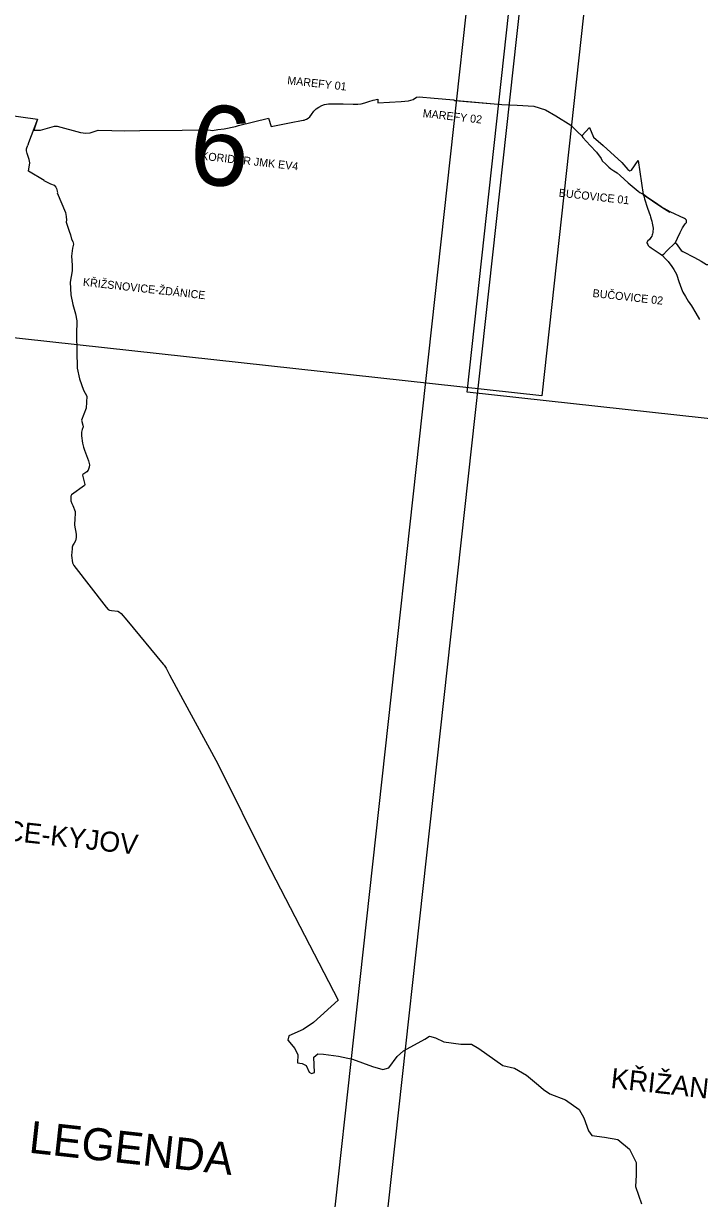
# Model space of a CAD drawing. Extents: x -678204 to -526855, y -1228851 to -1110393.
# Drawn here: x -574848 to -569781, y -1176918 to -1168109 of the extents above; entities that cross this region are included whole.
import ezdxf

# ---------------------------------------------------------------- set-up
doc = ezdxf.new("R2010")
doc.units = 0
for name, color, linetype in [('00_n_cyklo popisy detaily', 7, 'Continuous'), ('00_n_cyklo popisy ostatni', 7, 'Continuous'), ('00_n_cyklo provereni rekreacni hlavni', 7, 'Continuous'), ('00_n_cyklo provereni vedlejsi', 7, 'Continuous'), ('00_n_cyklo prujezdne rekreacni hlavni', 7, 'Continuous'), ('00_n_cyklo prujezdne rekreacni vedlejsi', 7, 'Continuous'), ('00_n_cyklo trasovani rekreacni hlavni', 7, 'Continuous'), ('00_n_cyklo trasovani rekreacni vedlejsi', 7, 'Continuous'), ('00_n_legenda popisy', 7, 'Continuous'), ('_HELP', 7, 'Continuous'), ('_HELP BIG', 7, 'Continuous')]:
    doc.layers.add(name, color=color, linetype=linetype)

msp = doc.modelspace()

# ---------------------------------------------------------------- linework, layer by layer
at = {"layer": '00_n_cyklo provereni rekreacni hlavni'}
for points in [[(-572752.6, -1168833.3), (-572743.5, -1168832.2), (-572734.1, -1168829.4), (-572726.2, -1168827), (-572714.5, -1168819.7), (-572702.8, -1168808.7), (-572689, -1168790.4), (-572671.6, -1168766.2), (-572655, -1168749.4), (-572635.4, -1168735), (-572613.1, -1168723.4), (-572590.8, -1168716.2), (-572560.8, -1168711.1), (-572536.1, -1168711.1), (-572502.9, -1168711.2), (-572452.9, -1168711.7), (-572376.3, -1168713.6), (-572343, -1168714), (-572317.4, -1168711.6), (-572289.7, -1168704.3), (-572260.7, -1168694.5), (-572228.1, -1168683.2), (-572192.5, -1168676.8)], [(-572192.6, -1168702.3), (-572017.1, -1168693.1), (-571963.4, -1168689.5), (-571928.6, -1168678.7), (-571903.2, -1168660.1), (-571882.9, -1168659.2), (-571770.8, -1168667.8), (-571623.1, -1168680.5), (-571613.9, -1168685.2), (-571599.5, -1168686.4)], [(-570664.3, -1168952), (-570654.5, -1168962.3), (-570599.8, -1169023.2), (-570553, -1169073), (-570519.3, -1169121.7), (-570509.9, -1169137.5), (-570484.2, -1169163.1), (-570461.3, -1169184.9), (-570446.4, -1169197.6), (-570422.9, -1169213.3), (-570399.1, -1169227.2), (-570375.6, -1169247.3), (-570315.3, -1169303.2), (-570242.1, -1169366.2), (-570228.2, -1169375), (-570203, -1169389)], [(-570057.9, -1169849.1), (-570037.7, -1169870), (-570016.6, -1169893.4), (-569988.3, -1169929.6), (-569973.8, -1169953.2), (-569954.2, -1169989), (-569951.3, -1169996.6), (-569934.9, -1170042.6), (-569916.9, -1170098.3), (-569906.2, -1170122.2), (-569887.4, -1170155.1), (-569865.4, -1170191), (-569841.4, -1170226.5), (-569809.5, -1170280.8), (-569781.1, -1170328.1)]]:
    msp.add_lwpolyline(points, dxfattribs=at)
at = {"layer": '00_n_cyklo provereni vedlejsi'}
for points in [[(-574744.2, -1168826.8), (-574810.3, -1169003.7), (-574814.4, -1169020.3)], [(-574693.9, -1169285.8), (-574810.9, -1169216.2), (-574801.3, -1169153.8), (-574804.7, -1169129.6), (-574820.7, -1169084.3), (-574826.2, -1169062.5), (-574824.8, -1169049), (-574814.5, -1169021)], [(-574696, -1169286), (-574644.8, -1169309.6), (-574618.6, -1169320.5), (-574604.7, -1169335.1), (-574599.5, -1169345.7), (-574594.4, -1169376.4)], [(-574594.5, -1169377.5), (-574534, -1169525), (-574527.5, -1169555.7), (-574524.8, -1169582.3), (-574528.6, -1169596.6)], [(-574528.6, -1169596.6), (-574528.8, -1169597.3), (-574506.7, -1169665.1), (-574496.8, -1169692.7), (-574488, -1169724.7), (-574478.8, -1169743.1), (-574474.2, -1169762.4), (-574480, -1169793.4), (-574488.1, -1169853), (-574483, -1169920), (-574484, -1169963.6), (-574498.9, -1170049.2), (-574493.6, -1170142.2), (-574478.7, -1170214.9), (-574458.3, -1170285.7), (-574448.8, -1170338.8), (-574451.8, -1170440.1), (-574445.2, -1170691.9), (-574428.5, -1170773.3), (-574397.2, -1170856.7), (-574374.3, -1170903.7), (-574378.4, -1170993.4), (-574412.9, -1171082.1), (-574404.4, -1171120.6), (-574400.8, -1171133.1)]]:
    msp.add_lwpolyline(points, dxfattribs=at)
at = {"layer": '00_n_cyklo prujezdne rekreacni hlavni'}
for points in [[(-576599.9, -1168325), (-576538.9, -1168348.6), (-576495.6, -1168376), (-576473.9, -1168384), (-576454.4, -1168390.7), (-576419.3, -1168410.3), (-576234.4, -1168526.7), (-576118.7, -1168593.6), (-576055.3, -1168623.1), (-575996.7, -1168644.3), (-575952.7, -1168654.8), (-575532.5, -1168715.6), (-574742.7, -1168826.9), (-574771, -1168908.2)], [(-572192.5, -1168676.8), (-572192.5, -1168690.2), (-572192.6, -1168702.3)], [(-571599.5, -1168686.4), (-571261.7, -1168715.8), (-571146.9, -1168719.8), (-571024.2, -1168729.2), (-570934.6, -1168755.2), (-570859.1, -1168800), (-570744.5, -1168871.2), (-570693.9, -1168923), (-570664.4, -1168951.8)], [(-574771, -1168908.2), (-574720.9, -1168907.8), (-574668.9, -1168893.3), (-574615.6, -1168878.4), (-574594.8, -1168878), (-574420.4, -1168926.8), (-574379.7, -1168930.9), (-574349.4, -1168929), (-574288.8, -1168907.3), (-574184.8, -1168912.1), (-574092.9, -1168912.8), (-573975.4, -1168911.9), (-573659.7, -1168908.2), (-573462.3, -1168906.8), (-573431.5, -1168910.9), (-573391.3, -1168903.6), (-573344.3, -1168898.7), (-573258, -1168881.9), (-573235.4, -1168872.5), (-573012, -1168818.6), (-572990.7, -1168880.5), (-572854.8, -1168853), (-572753, -1168833.3), (-572752.6, -1168833.3)], [(-570203, -1169389), (-570198.6, -1169404.1), (-570192.9, -1169423), (-570170, -1169494), (-570151.3, -1169549.3), (-570148.8, -1169557.2), (-570142.5, -1169576.6), (-570140.5, -1169584.1), (-570138.9, -1169590.4), (-570135.7, -1169605.2), (-570133.4, -1169619), (-570131.5, -1169630.3), (-570129.6, -1169642.8), (-570128.5, -1169650.2), (-570128.6, -1169652.1), (-570128.7, -1169654.4), (-570130, -1169663), (-570130.3, -1169665.1), (-570131, -1169674.8), (-570133.1, -1169685.4), (-570136.3, -1169694.4), (-570139.7, -1169702.4), (-570145.9, -1169712.3), (-570151.8, -1169721.1), (-570157, -1169727.1), (-570170.6, -1169740.7), (-570172, -1169742.8), (-570173.3, -1169744.8), (-570174.6, -1169747.2), (-570175.3, -1169749.2), (-570175.5, -1169750.9), (-570175.5, -1169751.6), (-570175.5, -1169752.4), (-570175.2, -1169753.4), (-570173.4, -1169758.3), (-570169.5, -1169766.4), (-570165.7, -1169772.9), (-570161.9, -1169777.6), (-570158.8, -1169780.6), (-570154.2, -1169783.7), (-570143, -1169790.9), (-570075.4, -1169836.4), (-570057.9, -1169849.1)]]:
    msp.add_lwpolyline(points, dxfattribs=at)
at = {"layer": '00_n_cyklo prujezdne rekreacni vedlejsi'}
for points in [[(-570664.4, -1168951.8), (-570606.1, -1168887.7), (-570574.9, -1168960.3), (-570503.9, -1169023.6), (-570363.4, -1169150.2), (-570319.1, -1169203.1), (-570304.6, -1169213.5), (-570290.6, -1169208.5), (-570241.2, -1169136.2)], [(-570664.4, -1168951.8), (-570664.4, -1168951.8)], [(-570241.2, -1169136.2), (-570202.7, -1169389.9)], [(-574400.8, -1171133.1), (-574408.6, -1171152.5), (-574413.7, -1171172.3), (-574414.1, -1171200.9), (-574405.9, -1171256.4), (-574397.7, -1171284.4), (-574390.9, -1171306.5), (-574360.7, -1171387.7), (-574352.5, -1171417.1), (-574356.2, -1171435.8), (-574363, -1171458.7), (-574374.2, -1171469.6), (-574404.2, -1171490.7), (-574404.9, -1171494.8), (-574388.6, -1171565.3), (-574390.3, -1171571.4), (-574487.9, -1171643.2), (-574494.5, -1171653.4), (-574494.5, -1171687.3), (-574486.8, -1171706.4), (-574477.2, -1171722.5), (-574460.3, -1171768), (-574459.6, -1171788.1), (-574464, -1171816.7), (-574465.4, -1171869.2), (-574454.5, -1171937.3), (-574452.8, -1171961.5), (-574458.2, -1171987.1), (-574469.5, -1172006.1), (-574479, -1172020.1), (-574483.4, -1172035.4), (-574484.4, -1172047), (-574487.4, -1172096.9), (-574479.7, -1172152.3), (-574471.4, -1172171.4), (-574229.4, -1172483.8), (-574213, -1172502.7), (-574202.8, -1172507.1), (-574187.8, -1172510.2), (-574141.5, -1172515.9), (-574128.6, -1172522.4), (-574117, -1172531.6), (-574074.8, -1172581.4), (-573801.7, -1172911.6), (-573793.2, -1172920.8), (-573777.8, -1172942.6), (-573754.2, -1172990.9), (-573653.9, -1173177.1), (-573391, -1173659.1), (-573029.7, -1174389.8), (-572489.5, -1175430.5)], [(-572489.5, -1175430.5), (-572673.6, -1175600), (-572752.2, -1175651.2), (-572860.5, -1175699.7), (-572867.4, -1175730.9), (-572814, -1175793.6), (-572791, -1175842.2), (-572794, -1175902.3), (-572758.9, -1175906.1), (-572728.5, -1175920.1), (-572705.9, -1175972.3), (-572689.1, -1175981.2), (-572666.9, -1175973), (-572672.1, -1175858.8), (-572641, -1175833.9), (-572598.5, -1175835), (-572486.7, -1175850.8), (-572382.7, -1175872.9), (-572232.7, -1175928.4), (-572153.6, -1175951.3), (-572109.6, -1175938.4), (-572047, -1175852.9), (-571999.9, -1175812), (-571841.1, -1175722.9), (-571805.7, -1175700.9), (-571760.9, -1175712.9), (-571697, -1175744.8), (-571571.1, -1175762.2), (-571489.3, -1175760.5), (-571436.3, -1175794.7), (-571255, -1175921.1), (-571168.5, -1175941.3), (-571078.5, -1175993.8), (-570987.2, -1176067.7), (-570951.7, -1176100), (-570902.2, -1176133.8), (-570786.5, -1176178.5), (-570684.3, -1176250.1), (-570648.8, -1176314.3), (-570613.3, -1176410.5), (-570588.7, -1176445.2), (-570494.4, -1176459.1), (-570393.5, -1176477.2), (-570305.4, -1176547.3), (-570256.2, -1176648.5), (-570256, -1176744.4), (-570261.8, -1176829), (-570215.6, -1176958.3)]]:
    msp.add_lwpolyline(points, dxfattribs=at)
at = {"layer": '00_n_cyklo trasovani rekreacni hlavni'}
for points in [[(-576599.9, -1168325), (-576538.9, -1168348.6), (-576495.6, -1168376), (-576473.9, -1168384), (-576454.4, -1168390.7), (-576419.3, -1168410.3), (-576234.4, -1168526.7), (-576118.7, -1168593.6), (-576055.3, -1168623.1), (-575996.7, -1168644.3), (-575952.7, -1168654.8), (-575532.5, -1168715.6), (-574742.7, -1168826.9), (-574771, -1168908.2)], [(-572752.6, -1168833.3), (-572743.5, -1168832.2), (-572734.1, -1168829.4), (-572726.2, -1168827), (-572714.5, -1168819.7), (-572702.8, -1168808.7), (-572689, -1168790.4), (-572671.6, -1168766.2), (-572655, -1168749.4), (-572635.4, -1168735), (-572613.1, -1168723.4), (-572590.8, -1168716.2), (-572560.8, -1168711.1), (-572536.1, -1168711.1), (-572502.9, -1168711.2), (-572452.9, -1168711.7), (-572376.3, -1168713.6), (-572343, -1168714), (-572317.4, -1168711.6), (-572289.7, -1168704.3), (-572260.7, -1168694.5), (-572228.1, -1168683.2), (-572192.5, -1168676.8)], [(-572192.6, -1168702.3), (-572017.1, -1168693.1), (-571963.4, -1168689.5), (-571928.6, -1168678.7), (-571903.2, -1168660.1), (-571882.9, -1168659.2), (-571770.8, -1168667.8), (-571623.1, -1168680.5), (-571613.9, -1168685.2), (-571261.7, -1168715.8), (-571146.9, -1168719.8), (-571024.2, -1168729.2), (-570934.6, -1168755.2), (-570859.1, -1168800), (-570744.5, -1168871.2), (-570693.9, -1168923), (-570664.4, -1168951.8)], [(-572192.5, -1168676.8), (-572192.5, -1168690.2), (-572192.6, -1168702.3)], [(-574771, -1168908.2), (-574720.9, -1168907.8), (-574668.9, -1168893.3), (-574615.6, -1168878.4), (-574594.8, -1168878), (-574420.4, -1168926.8), (-574379.7, -1168930.9), (-574349.4, -1168929), (-574288.8, -1168907.3), (-574184.8, -1168912.1), (-574092.9, -1168912.8), (-573975.4, -1168911.9), (-573659.7, -1168908.2), (-573462.3, -1168906.8), (-573431.5, -1168910.9), (-573391.3, -1168903.6), (-573344.3, -1168898.7), (-573258, -1168881.9), (-573235.4, -1168872.5), (-573012, -1168818.6), (-572990.7, -1168880.5), (-572854.8, -1168853), (-572753, -1168833.3), (-572752.6, -1168833.3)], [(-570664.3, -1168952), (-570654.5, -1168962.3), (-570599.8, -1169023.2), (-570553, -1169073), (-570519.3, -1169121.7), (-570509.9, -1169137.5), (-570484.2, -1169163.1), (-570461.3, -1169184.9), (-570446.4, -1169197.6), (-570422.9, -1169213.3), (-570399.1, -1169227.2), (-570375.6, -1169247.3), (-570315.3, -1169303.2), (-570242.1, -1169366.2), (-570228.2, -1169375), (-570203, -1169389)], [(-569961, -1169750.1), (-569945, -1169719.1), (-569925.4, -1169675.2), (-569909.1, -1169641.6), (-569887.7, -1169611.2), (-569877.8, -1169600.2), (-569879.4, -1169584), (-569886.5, -1169575.9), (-569894.6, -1169571), (-570000, -1169521.3), (-570068, -1169483.1), (-570119, -1169449.5), (-570174.8, -1169409.9), (-570203, -1169389)], [(-570202.7, -1169389.9), (-570063.8, -1169486.6), (-570003.7, -1169523.3)], [(-569955.9, -1169758.1), (-569919.5, -1169809.5), (-569905.7, -1169817.7), (-569817.9, -1169863.4), (-569768.8, -1169890.9), (-569727.6, -1169916.8), (-569717.5, -1169915.9), (-569708.3, -1169911.5), (-569640.1, -1169849.5), (-569628.8, -1169850.1), (-569620.2, -1169857.1), (-569582.3, -1169888.6), (-569573.6, -1169894.9), (-569450.9, -1169975.2), (-569424.2, -1169988.2), (-569366.4, -1170014.6), (-569348, -1170017.9), (-569316.4, -1170022), (-569266.7, -1170025.5), (-569227, -1170028.5), (-569180.9, -1170053)]]:
    msp.add_lwpolyline(points, dxfattribs=at)
at = {"layer": '00_n_cyklo trasovani rekreacni vedlejsi'}
for points in [[(-574744.2, -1168826.8), (-574810.3, -1169003.7), (-574814.4, -1169020.3)], [(-570664.4, -1168951.8), (-570606.1, -1168887.7), (-570574.9, -1168960.3), (-570503.9, -1169023.6), (-570363.4, -1169150.2), (-570319.1, -1169203.1), (-570304.6, -1169213.5), (-570290.6, -1169208.5), (-570241.2, -1169136.2)], [(-570664.4, -1168951.8), (-570664.4, -1168951.8)], [(-574693.9, -1169285.8), (-574810.9, -1169216.2), (-574801.3, -1169153.8), (-574804.7, -1169129.6), (-574820.7, -1169084.3), (-574826.2, -1169062.5), (-574824.8, -1169049), (-574814.5, -1169021)], [(-570241.2, -1169136.2), (-570202.7, -1169389.9)], [(-574696, -1169286), (-574644.8, -1169309.6), (-574618.6, -1169320.5), (-574604.7, -1169335.1), (-574599.5, -1169345.7), (-574594.4, -1169376.4)], [(-574594.5, -1169377.5), (-574534, -1169525), (-574527.5, -1169555.7), (-574524.8, -1169582.3), (-574528.6, -1169596.6)], [(-570203, -1169389), (-570198.6, -1169404.1), (-570192.9, -1169423), (-570170, -1169494), (-570151.3, -1169549.3), (-570148.8, -1169557.2), (-570142.5, -1169576.6), (-570140.5, -1169584.1), (-570138.9, -1169590.4), (-570135.7, -1169605.2), (-570133.4, -1169619), (-570131.5, -1169630.3), (-570129.6, -1169642.8), (-570128.5, -1169650.2), (-570128.6, -1169652.1), (-570128.7, -1169654.4), (-570130, -1169663), (-570130.3, -1169665.1), (-570131, -1169674.8), (-570133.1, -1169685.4), (-570136.3, -1169694.4), (-570139.7, -1169702.4), (-570145.9, -1169712.3), (-570151.8, -1169721.1), (-570157, -1169727.1), (-570170.6, -1169740.7), (-570172, -1169742.8), (-570173.3, -1169744.8), (-570174.6, -1169747.2), (-570175.3, -1169749.2), (-570175.5, -1169750.9), (-570175.5, -1169751.6), (-570175.5, -1169752.4), (-570175.2, -1169753.4), (-570173.4, -1169758.3), (-570169.5, -1169766.4), (-570165.7, -1169772.9), (-570161.9, -1169777.6), (-570158.8, -1169780.6), (-570154.2, -1169783.7), (-570143, -1169790.9), (-570075.4, -1169836.4), (-570064.9, -1169844)], [(-574528.6, -1169596.6), (-574528.8, -1169597.3), (-574506.7, -1169665.1), (-574496.8, -1169692.7), (-574488, -1169724.7), (-574478.8, -1169743.1), (-574474.2, -1169762.4), (-574480, -1169793.4), (-574488.1, -1169853), (-574483, -1169920), (-574484, -1169963.6), (-574498.9, -1170049.2), (-574493.6, -1170142.2), (-574478.7, -1170214.9), (-574458.3, -1170285.7), (-574448.8, -1170338.8), (-574451.8, -1170440.1), (-574445.2, -1170691.9), (-574428.5, -1170773.3), (-574397.2, -1170856.7), (-574374.3, -1170903.7), (-574378.4, -1170993.4), (-574412.9, -1171082.1), (-574404.4, -1171120.6), (-574400.8, -1171133.1)], [(-569955.9, -1169758.1), (-569960.7, -1169751.7), (-570028.8, -1169816.2), (-570051.4, -1169841.6), (-570059.5, -1169845.3), (-570064.9, -1169844)], [(-574400.8, -1171133.1), (-574408.6, -1171152.5), (-574413.7, -1171172.3), (-574414.1, -1171200.9), (-574405.9, -1171256.4), (-574397.7, -1171284.4), (-574390.9, -1171306.5), (-574360.7, -1171387.7), (-574352.5, -1171417.1), (-574356.2, -1171435.8), (-574363, -1171458.7), (-574374.2, -1171469.6), (-574404.2, -1171490.7), (-574404.9, -1171494.8), (-574388.6, -1171565.3), (-574390.3, -1171571.4), (-574487.9, -1171643.2), (-574494.5, -1171653.4), (-574494.5, -1171687.3), (-574486.8, -1171706.4), (-574477.2, -1171722.5), (-574460.3, -1171768), (-574459.6, -1171788.1), (-574464, -1171816.7), (-574465.4, -1171869.2), (-574454.5, -1171937.3), (-574452.8, -1171961.5), (-574458.2, -1171987.1), (-574469.5, -1172006.1), (-574479, -1172020.1), (-574483.4, -1172035.4), (-574484.4, -1172047), (-574487.4, -1172096.9), (-574479.7, -1172152.3), (-574471.4, -1172171.4), (-574229.4, -1172483.8), (-574213, -1172502.7), (-574202.8, -1172507.1), (-574187.8, -1172510.2), (-574141.5, -1172515.9), (-574128.6, -1172522.4), (-574117, -1172531.6), (-574074.8, -1172581.4), (-573801.7, -1172911.6), (-573793.2, -1172920.8), (-573777.8, -1172942.6), (-573754.2, -1172990.9), (-573653.9, -1173177.1), (-573391, -1173659.1), (-573029.7, -1174389.8), (-572489.5, -1175430.5)], [(-572489.5, -1175430.5), (-572673.6, -1175600), (-572752.2, -1175651.2), (-572860.5, -1175699.7), (-572867.4, -1175730.9), (-572814, -1175793.6), (-572791, -1175842.2), (-572794, -1175902.3), (-572758.9, -1175906.1), (-572728.5, -1175920.1), (-572705.9, -1175972.3), (-572689.1, -1175981.2), (-572666.9, -1175973), (-572672.1, -1175858.8), (-572641, -1175833.9), (-572598.5, -1175835), (-572486.7, -1175850.8), (-572382.7, -1175872.9), (-572232.7, -1175928.4), (-572153.6, -1175951.3), (-572109.6, -1175938.4), (-572047, -1175852.9), (-571999.9, -1175812), (-571841.1, -1175722.9), (-571805.7, -1175700.9), (-571760.9, -1175712.9), (-571697, -1175744.8), (-571571.1, -1175762.2), (-571489.3, -1175760.5), (-571436.3, -1175794.7), (-571255, -1175921.1), (-571168.5, -1175941.3), (-571078.5, -1175993.8), (-570987.2, -1176067.7), (-570951.7, -1176100), (-570902.2, -1176133.8), (-570786.5, -1176178.5), (-570684.3, -1176250.1), (-570648.8, -1176314.3), (-570613.3, -1176410.5), (-570588.7, -1176445.2), (-570494.4, -1176459.1), (-570393.5, -1176477.2), (-570305.4, -1176547.3), (-570256.2, -1176648.5), (-570256, -1176744.4), (-570261.8, -1176829), (-570215.6, -1176958.3)]]:
    msp.add_lwpolyline(points, dxfattribs=at)
at = {"layer": '_HELP'}
for points in [[(-575309.6, -1167024.7), (-570595.1, -1167542.4), (-570963.7, -1170899.9), (-575678.3, -1170382.2)], [(-571154.5, -1167514.1), (-566440, -1168031.8), (-566808.6, -1171389.3), (-571523.2, -1170871.6)]]:
    msp.add_lwpolyline(points, close=True, dxfattribs=at)
at = {"layer": '_HELP BIG'}
for points in [[(-572713.2, -1182415), (-601000.5, -1179308.8), (-598788.5, -1159163.8), (-570501.1, -1162270)], [(-544826.9, -1185575), (-573114.2, -1182468.8), (-570902.2, -1162323.8), (-542614.8, -1165430)]]:
    msp.add_lwpolyline(points, close=True, dxfattribs=at)

# ---------------------------------------------------------------- texts
at = {"layer": '00_n_cyklo popisy detaily'}
for s, p in [('MAREFY 01', (-572873.1, -1168562.8)), ('MAREFY 02', (-571858, -1168810.1)), ('KORIDOR JMK EV4', (-573518.6, -1169129.4)), ('BUČOVICE 01', (-570838.2, -1169406.4)), ('KŘIŽSNOVICE-ŽDÁNICE', (-574404.9, -1170074.8)), ('BUČOVICE 02', (-570585, -1170158.9))]:
    msp.add_text(s, height=60, rotation=353.68355, dxfattribs=at).set_placement(p)
at = {"layer": '00_n_cyklo popisy ostatni'}
for p in [(-577012.2, -1174007.5), (-570451.5, -1176088.9)]:
    msp.add_text('KŘIŽANOVICE-ŽDÁNICE-KYJOV', height=150, rotation=353.68355, dxfattribs=at).set_placement(p)
at = {"layer": '00_n_legenda popisy'}
msp.add_text('LEGENDA', height=240, rotation=353.68355, dxfattribs=at).set_placement((-574814.3, -1176574))
at = {"layer": '_HELP'}
msp.add_text('6', height=600, rotation=353.68355, dxfattribs=at).set_placement((-573628.4, -1169297.4))

doc.saveas('drawing.dxf')
